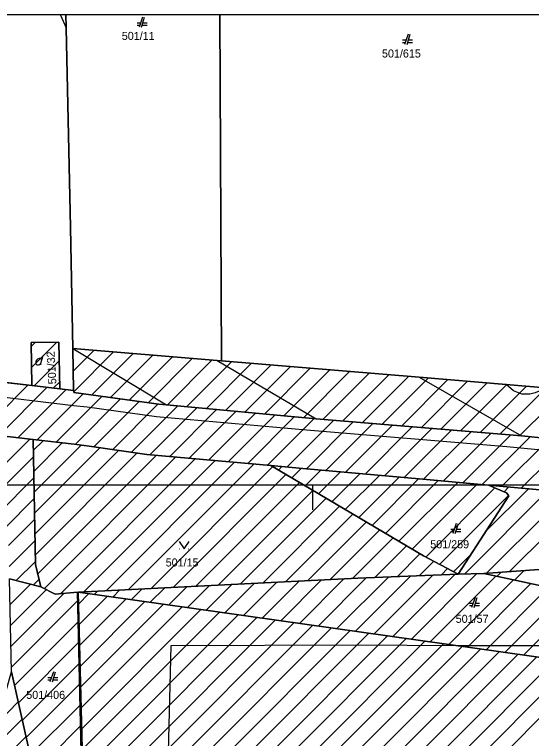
# Model space of a CAD drawing. Extents: x -264309 to -263505, y -1242443 to -1241763.
# Drawn here: x -263955.2 to -263852.2, y -1242101 to -1241957 of the extents above; entities that cross this region are included whole.
import ezdxf

# ---------------------------------------------------------------- set-up
doc = ezdxf.new("R2010")
doc.units = 0
for name, color, linetype in [('KFA_SO_50-2_POZIARNY_VODOVOD_TRASA', 7, 'Continuous'), ('KN_2019_08_16_KLADPAR', 7, 'Continuous'), ('KN_2019_08_16_ZAPPAR', 7, 'Continuous'), ('RAM_NA_TLAC_10xA4_1-500', 7, 'Continuous'), ('SRAFY_PARCELY', 7, 'Continuous')]:
    doc.layers.add(name, color=color, linetype=linetype)

msp = doc.modelspace()

# ---------------------------------------------------------------- linework, layer by layer
at = {"layer": 'KFA_SO_50-2_POZIARNY_VODOVOD_TRASA'}
msp.add_lwpolyline([(-263924.93, -1242185.13), (-263924.15, -1242197.09), (-263924.3, -1242220.9), (-263924.1, -1242250.12), (-263913.99, -1242249.8), (-263886.91, -1242249.88), (-263867.71, -1242249.83), (-263837.26, -1242249.84), (-263828.16, -1242249.9), (-263787.99, -1242250.03), (-263788.2, -1242220.84), (-263788.2, -1242200.51), (-263788.09, -1242179.92), (-263788.06, -1242148.96), (-263787.92, -1242127.95), (-263787.95, -1242110.97), (-263788.13, -1242082.54), (-263828.43, -1242082.72), (-263836.78, -1242082.56), (-263867.31, -1242082.61), (-263886.71, -1242082.47), (-263924.08, -1242082.61), (-263924.64, -1242106.32), (-263924.48, -1242117.43)], close=True, dxfattribs=at)
at = {"layer": 'KN_2019_08_16_KLADPAR'}
for p, q in [((-263979.18, -1241956.96), (-263944.96, -1241956.96)), ((-263944.96, -1241956.96), (-263944.89, -1241959.62)), ((-263944.89, -1241959.62), (-263944.96, -1241956.96)), ((-263944.96, -1241956.96), (-263914.3, -1241956.96)), ((-263929.7, -1241957.48), (-263930.4, -1241959.48)), ((-263929.9, -1241959.48), (-263929.3, -1241957.48)), ((-263914.3, -1241956.96), (-263830.29, -1241956.96)), ((-263914, -1242025.89), (-263914.3, -1241956.96)), ((-263914.3, -1241956.96), (-263914, -1242025.89)), ((-263930.12, -1241958.68), (-263930.8, -1241958.68)), ((-263930.8, -1241959.08), (-263930.26, -1241959.08)), ((-263929.78, -1241959.08), (-263928.8, -1241959.08)), ((-263928.8, -1241958.68), (-263929.66, -1241958.68)), ((-263944.89, -1241959.62), (-263944.09, -1241999.37)), ((-263944.09, -1241999.37), (-263944.89, -1241959.62)), ((-263876.81, -1241960.9), (-263877.51, -1241962.9)), ((-263877.01, -1241962.9), (-263876.41, -1241960.9)), ((-263877.23, -1241962.1), (-263877.91, -1241962.1)), ((-263877.91, -1241962.5), (-263877.37, -1241962.5)), ((-263876.89, -1241962.5), (-263875.91, -1241962.5)), ((-263875.91, -1241962.1), (-263876.77, -1241962.1)), ((-263944.09, -1241999.37), (-263943.61, -1242023.45)), ((-263943.61, -1242023.45), (-263944.09, -1241999.37)), ((-263946.36, -1242022.14), (-263951.91, -1242022.22)), ((-263951.91, -1242022.22), (-263951.74, -1242030.76)), ((-263946.18, -1242031.43), (-263946.36, -1242022.14)), ((-263943.61, -1242023.45), (-263943.43, -1242031.76)), ((-263914.84, -1242025.82), (-263943.61, -1242023.45)), ((-263949.79, -1242025.7), (-263949.52, -1242024.8)), ((-263914, -1242025.89), (-263914.84, -1242025.82)), ((-263874.62, -1242029.15), (-263914, -1242025.89)), ((-263951.74, -1242030.76), (-263970.71, -1242028.65)), ((-263857.26, -1242030.58), (-263874.62, -1242029.15)), ((-263849.43, -1242031.23), (-263857.26, -1242030.58)), ((-263943.43, -1242031.76), (-263946.18, -1242031.43)), ((-263867.19, -1242058.24), (-263867.89, -1242060.24)), ((-263867.39, -1242060.24), (-263866.79, -1242058.24)), ((-263867.61, -1242059.44), (-263868.29, -1242059.44)), ((-263868.29, -1242059.84), (-263867.75, -1242059.84)), ((-263867.27, -1242059.84), (-263866.29, -1242059.84)), ((-263866.29, -1242059.44), (-263867.15, -1242059.44)), ((-263922.36, -1242063.31), (-263922.26, -1242063.31)), ((-263920.56, -1242063.31), (-263920.46, -1242063.31)), ((-263863.45, -1242072.99), (-263864.15, -1242074.99)), ((-263863.65, -1242074.99), (-263863.05, -1242072.99)), ((-263863.87, -1242074.19), (-263864.55, -1242074.19)), ((-263862.55, -1242074.19), (-263863.41, -1242074.19)), ((-263864.55, -1242074.59), (-263864.01, -1242074.59)), ((-263863.53, -1242074.59), (-263862.55, -1242074.59)), ((-263947.45, -1242087.77), (-263948.15, -1242089.77)), ((-263947.65, -1242089.77), (-263947.05, -1242087.77)), ((-263947.87, -1242088.97), (-263948.55, -1242088.97)), ((-263948.55, -1242089.37), (-263948.01, -1242089.37)), ((-263947.53, -1242089.37), (-263946.55, -1242089.37)), ((-263946.55, -1242088.97), (-263947.41, -1242088.97))]:
    msp.add_line(p, q, dxfattribs=at)
for points in [[(-263951.74, -1242030.76), (-263951.91, -1242022.22), (-263946.36, -1242022.14), (-263946.18, -1242031.43)], [(-263859.25, -1242051.26), (-263857.2, -1242052.16), (-263856.75, -1242052.73), (-263866.84, -1242068.34), (-263873.71, -1242064.69), (-263904.14, -1242046.74), (-263897.8, -1242047.3), (-263874.58, -1242049.37), (-263860.75, -1242050.61)], [(-263860.75, -1242050.61), (-263838.09, -1242052.7), (-263834.98, -1242053.91), (-263833.09, -1242055.88), (-263832.11, -1242058.36), (-263832.17, -1242061), (-263833.22, -1242063.52), (-263835.57, -1242065.69), (-263837.8, -1242066.47), (-263861.71, -1242068.19), (-263866.84, -1242068.34), (-263856.75, -1242052.73), (-263857.2, -1242052.16), (-263859.25, -1242051.26)], [(-263866.84, -1242068.34), (-263861.71, -1242068.19), (-263831.68, -1242074.63), (-263824.48, -1242063.97), (-263825.06, -1242076), (-263823.41, -1242079.44), (-263822.15, -1242081.25), (-263808.5, -1242089.28), (-263825.79, -1242087.54), (-263827.51, -1242086.49), (-263831.22, -1242086.53), (-263833.02, -1242086.81), (-263846.54, -1242085.45), (-263942.54, -1242071.9), (-263913.4, -1242070.43), (-263886.83, -1242069.14)], [(-263945.92, -1242287.35), (-263949.74, -1242287.63), (-263949.41, -1242196.68), (-263949.38, -1242187.85), (-263949.49, -1242175.05), (-263949.55, -1242159.39), (-263950.14, -1242129.96), (-263950.48, -1242111.43), (-263955.8, -1242087.79), (-263956.24, -1242069.24), (-263949.96, -1242070.83), (-263947.13, -1242072.33), (-263942.68, -1242071.91), (-263941.47, -1242124.08), (-263944.59, -1242125.87), (-263946.11, -1242129.79), (-263945.51, -1242159.3), (-263945.41, -1242187.87)], [(-263942.54, -1242071.9), (-263846.54, -1242085.45), (-263846.27, -1242096.79), (-263846.29, -1242099.09), (-263845.63, -1242123.54), (-263845.17, -1242145.54), (-263890.62, -1242146.65), (-263890.76, -1242147.37), (-263921.62, -1242147.75), (-263934.65, -1242147.91), (-263935.23, -1242123.81), (-263941.18, -1242123.7)]]:
    msp.add_lwpolyline(points, close=True, dxfattribs=at)
for points in [[(-263773.94, -1242049.27), (-263789.68, -1242047.57), (-263790.18, -1242047.53), (-263806.03, -1242046.03), (-263821.84, -1242044.14), (-263837.98, -1242042.2), (-263848.99, -1242041.32), (-263854.22, -1242040.83), (-263895.14, -1242037.44), (-263924.96, -1242034.66), (-263926.48, -1242034.52), (-263943.42, -1242032.17), (-263943.43, -1242031.76), (-263943.61, -1242023.45), (-263914.84, -1242025.82), (-263914, -1242025.89), (-263874.62, -1242029.15), (-263857.26, -1242030.58), (-263849.43, -1242031.23), (-263836.79, -1242032.27), (-263829.96, -1242032.95), (-263750.04, -1242040.89)], [(-263949.97, -1242026.69), (-263949.97, -1242026.42), (-263949.79, -1242025.7), (-263949.88, -1242025.52), (-263950.06, -1242025.43), (-263950.33, -1242025.43), (-263950.6, -1242025.52), (-263950.78, -1242025.7), (-263950.96, -1242025.97), (-263950.96, -1242026.33), (-263950.87, -1242026.6), (-263950.69, -1242026.69), (-263950.42, -1242026.69), (-263950.24, -1242026.6), (-263949.97, -1242026.42)], [(-263970.71, -1242028.65), (-263951.74, -1242030.76), (-263946.18, -1242031.43), (-263943.43, -1242031.76), (-263943.42, -1242032.17), (-263926.48, -1242034.52), (-263924.96, -1242034.66), (-263895.14, -1242037.44), (-263854.22, -1242040.83), (-263848.99, -1242041.32), (-263837.98, -1242042.2), (-263821.84, -1242044.14), (-263806.03, -1242046.03), (-263790.18, -1242047.53), (-263789.68, -1242047.57), (-263773.94, -1242049.27)], [(-263958.98, -1242040.66), (-263951.52, -1242041.54), (-263951.02, -1242066.42), (-263949.96, -1242070.83), (-263956.24, -1242069.24)], [(-263838.09, -1242052.7), (-263860.75, -1242050.61), (-263874.58, -1242049.37), (-263897.8, -1242047.3), (-263904.14, -1242046.74), (-263928.83, -1242044.55), (-263940.32, -1242042.89), (-263943.31, -1242042.48), (-263951.52, -1242041.54), (-263958.98, -1242040.66)], [(-263941.47, -1242124.08), (-263942.68, -1242071.91), (-263947.13, -1242072.33), (-263949.96, -1242070.83), (-263951.02, -1242066.42), (-263951.52, -1242041.54), (-263943.31, -1242042.48), (-263940.32, -1242042.89), (-263928.83, -1242044.55), (-263904.14, -1242046.74), (-263873.71, -1242064.69), (-263866.84, -1242068.34), (-263886.83, -1242069.14), (-263913.4, -1242070.43), (-263942.54, -1242071.9), (-263941.18, -1242123.7)], [(-263922.41, -1242061.81), (-263921.41, -1242063.31), (-263920.41, -1242061.81)], [(-263831.68, -1242074.63), (-263861.71, -1242068.19), (-263837.8, -1242066.47)], [(-263970.22, -1242106.22), (-263970.24, -1242093.63), (-263970.38, -1242092.72), (-263963.73, -1242092.7), (-263963.72, -1242093.73), (-263959.83, -1242093.59), (-263956.8, -1242091.26), (-263955.8, -1242087.79), (-263950.48, -1242111.43)]]:
    msp.add_lwpolyline(points, dxfattribs=at)
at = {"layer": 'KN_2019_08_16_ZAPPAR'}
for p, q in [((-263943.61, -1242023.45), (-263924.96, -1242034.66)), ((-263914.84, -1242025.82), (-263895.14, -1242037.44)), ((-263874.62, -1242029.15), (-263854.22, -1242040.83)), ((-263852.57, -1242032.52), (-263854.16, -1242032.48))]:
    msp.add_line(p, q, dxfattribs=at)
for points in [[(-263946.2, -1241956.96), (-263946.07, -1241957.08), (-263944.89, -1241959.62)], [(-264009.05, -1242025.11), (-264007.06, -1242027.03), (-264004.88, -1242027.82), (-264001.52, -1242027.99), (-263958.32, -1242033), (-263951.68, -1242033.75), (-263943.48, -1242034.79), (-263940.72, -1242035.02), (-263926.91, -1242036.98), (-263897.04, -1242039.59), (-263857.13, -1242042.91), (-263837.1, -1242044.85)], [(-263854.16, -1242032.48), (-263855.79, -1242031.87), (-263857.26, -1242030.58)], [(-263849.43, -1242031.23), (-263850.37, -1242031.77), (-263851.47, -1242032.24), (-263852.57, -1242032.52)]]:
    msp.add_lwpolyline(points, dxfattribs=at)
at = {"layer": 'RAM_NA_TLAC_10xA4_1-500'}
msp.add_line((-263895.83, -1242050.54), (-263895.83, -1242055.54), dxfattribs=at)
msp.add_lwpolyline([(-264210.83, -1242050.54), (-264105.83, -1242050.54), (-264000.83, -1242050.54), (-263895.83, -1242050.54), (-263790.83, -1242050.54), (-263685.83, -1242050.54), (-263685.83, -1242199.04), (-263685.83, -1242347.54), (-263790.83, -1242347.54), (-263895.83, -1242347.54), (-264000.83, -1242347.54), (-264105.83, -1242347.54), (-264210.83, -1242347.54), (-264210.83, -1242199.04)], close=True, dxfattribs=at)
at = {"layer": 'SRAFY_PARCELY'}
for p, q in [((-263951.89, -1242023.02), (-263951.08, -1242022.21)), ((-263951.81, -1242027.18), (-263946.78, -1242022.15)), ((-263943.6, -1242023.76), (-263943.32, -1242023.47)), ((-263943.51, -1242027.91), (-263939.4, -1242023.8)), ((-263943.42, -1242032.06), (-263935.48, -1242024.12)), ((-263939.79, -1242032.67), (-263931.56, -1242024.44)), ((-263936.06, -1242033.19), (-263927.64, -1242024.77)), ((-263932.34, -1242033.71), (-263923.72, -1242025.09)), ((-263928.61, -1242034.22), (-263919.8, -1242025.41)), ((-263951.21, -1242030.82), (-263946.29, -1242025.9)), ((-263924.82, -1242034.67), (-263915.88, -1242025.73)), ((-263920.94, -1242035.03), (-263911.96, -1242026.06)), ((-263917.06, -1242035.4), (-263908.04, -1242026.38)), ((-263913.18, -1242035.76), (-263904.13, -1242026.71)), ((-263909.3, -1242036.12), (-263900.21, -1242027.03)), ((-263905.42, -1242036.48), (-263896.29, -1242027.36)), ((-263901.53, -1242036.84), (-263892.37, -1242027.68)), ((-263897.65, -1242037.21), (-263888.45, -1242028)), ((-263893.76, -1242037.55), (-263884.53, -1242028.33)), ((-263889.84, -1242037.88), (-263880.62, -1242028.65)), ((-263885.92, -1242038.2), (-263876.7, -1242028.98)), ((-263882.01, -1242038.53), (-263872.78, -1242029.3)), ((-263878.09, -1242038.85), (-263868.86, -1242029.62)), ((-263962.12, -1242040.29), (-263952.5, -1242030.67)), ((-263958.32, -1242040.74), (-263948.71, -1242031.12)), ((-263947.43, -1242031.28), (-263946.21, -1242030.06)), ((-263874.17, -1242039.18), (-263864.94, -1242029.95)), ((-263870.25, -1242039.5), (-263861.02, -1242030.27)), ((-263866.33, -1242039.83), (-263857.1, -1242030.59)), ((-263862.42, -1242040.15), (-263853.18, -1242030.92)), ((-263954.53, -1242041.19), (-263944.92, -1242031.58)), ((-263950.73, -1242041.63), (-263941.53, -1242032.43)), ((-263858.5, -1242040.48), (-263849.27, -1242031.24)), ((-263854.58, -1242040.8), (-263845.35, -1242031.57)), ((-263946.92, -1242042.07), (-263937.81, -1242032.95)), ((-263943.12, -1242042.51), (-263934.08, -1242033.47)), ((-263939.4, -1242043.02), (-263930.36, -1242033.98)), ((-263935.69, -1242043.56), (-263926.63, -1242034.5)), ((-263931.98, -1242044.09), (-263922.75, -1242034.87)), ((-263928.25, -1242044.6), (-263918.87, -1242035.23)), ((-263924.35, -1242044.95), (-263914.99, -1242035.59)), ((-263920.45, -1242045.29), (-263911.11, -1242035.95)), ((-263916.56, -1242045.64), (-263907.23, -1242036.31)), ((-263912.66, -1242045.98), (-263903.35, -1242036.67)), ((-263908.76, -1242046.33), (-263899.47, -1242037.04)), ((-263904.87, -1242046.68), (-263895.59, -1242037.4)), ((-263900.97, -1242047.02), (-263891.67, -1242037.73)), ((-263897.07, -1242047.37), (-263887.76, -1242038.05)), ((-263893.17, -1242047.71), (-263883.84, -1242038.38)), ((-263889.28, -1242048.06), (-263879.92, -1242038.7)), ((-263885.38, -1242048.41), (-263876, -1242039.03)), ((-263881.49, -1242048.75), (-263872.08, -1242039.35)), ((-263877.59, -1242049.1), (-263868.17, -1242039.67)), ((-263873.7, -1242049.45), (-263864.25, -1242040)), ((-263869.8, -1242049.8), (-263860.33, -1242040.32)), ((-263865.91, -1242050.15), (-263856.41, -1242040.65)), ((-263862.02, -1242050.5), (-263852.51, -1242040.99)), ((-263963.98, -1242053.27), (-263952.17, -1242041.46)), ((-263951.48, -1242043.71), (-263949.53, -1242041.77)), ((-263951.39, -1242047.87), (-263945.73, -1242042.2)), ((-263951.31, -1242052.03), (-263941.95, -1242042.67)), ((-263858.13, -1242050.85), (-263848.63, -1242041.35)), ((-263854.25, -1242051.21), (-263844.7, -1242041.66)), ((-263951.23, -1242056.19), (-263938.23, -1242043.19)), ((-263951.14, -1242060.35), (-263934.52, -1242043.73)), ((-263961.07, -1242054.6), (-263951.45, -1242044.98)), ((-263951.06, -1242064.51), (-263930.81, -1242044.26)), ((-263950.58, -1242068.27), (-263927.02, -1242044.71)), ((-263949.26, -1242071.2), (-263923.12, -1242045.06)), ((-263946.05, -1242072.23), (-263919.23, -1242045.4)), ((-263941.42, -1242071.84), (-263915.33, -1242045.75)), ((-263936.96, -1242071.62), (-263911.43, -1242046.09)), ((-263932.49, -1242071.39), (-263907.53, -1242046.44)), ((-263928.02, -1242071.17), (-263903.8, -1242046.94)), ((-263902.65, -1242047.62), (-263901.97, -1242046.93)), ((-263899.98, -1242049.19), (-263898.07, -1242047.28)), ((-263897.32, -1242050.77), (-263894.17, -1242047.62)), ((-263894.65, -1242052.34), (-263890.28, -1242047.97)), ((-263891.98, -1242053.91), (-263886.38, -1242048.32)), ((-263958.48, -1242056.25), (-263951.37, -1242049.14)), ((-263923.55, -1242070.94), (-263901.13, -1242048.52)), ((-263889.31, -1242055.49), (-263882.49, -1242048.67)), ((-263886.64, -1242057.06), (-263878.59, -1242049.01)), ((-263883.97, -1242058.64), (-263874.7, -1242049.36)), ((-263881.3, -1242060.21), (-263870.8, -1242049.71)), ((-263919.08, -1242070.72), (-263898.46, -1242050.09)), ((-263878.64, -1242061.78), (-263866.91, -1242050.06)), ((-263875.97, -1242063.36), (-263863.02, -1242050.41)), ((-263873.28, -1242064.92), (-263859.51, -1242051.15)), ((-263861.36, -1242059.86), (-263852.84, -1242051.34)), ((-263860.64, -1242050.66), (-263860.61, -1242050.62)), ((-263857.69, -1242051.95), (-263856.72, -1242050.98)), ((-263914.62, -1242070.49), (-263895.79, -1242051.67)), ((-263870.51, -1242066.39), (-263856.8, -1242052.67)), ((-263865.56, -1242068.3), (-263848.95, -1242051.7)), ((-263861.16, -1242068.15), (-263845.07, -1242052.06)), ((-263856.59, -1242067.82), (-263841.19, -1242052.41)), ((-263957.13, -1242059.15), (-263951.28, -1242053.3)), ((-263910.16, -1242070.27), (-263893.12, -1242053.24)), ((-263905.7, -1242070.06), (-263890.45, -1242054.81)), ((-263901.24, -1242069.84), (-263887.78, -1242056.39)), ((-263956.39, -1242062.65), (-263951.2, -1242057.46)), ((-263896.78, -1242069.62), (-263885.12, -1242057.96)), ((-263892.32, -1242069.41), (-263882.45, -1242059.54)), ((-263887.86, -1242069.19), (-263879.78, -1242061.11)), ((-263956.3, -1242066.8), (-263951.12, -1242061.62)), ((-263883.43, -1242069), (-263877.11, -1242062.68)), ((-263879.01, -1242068.83), (-263874.44, -1242064.26)), ((-263954.85, -1242069.59), (-263951.03, -1242065.78)), ((-263874.59, -1242068.65), (-263871.7, -1242065.76)), ((-263867.74, -1242067.86), (-263864.32, -1242064.44)), ((-263870.17, -1242068.47), (-263868.93, -1242067.23)), ((-263883.57, -1242080.22), (-263871.89, -1242068.54)), ((-263879.85, -1242080.75), (-263867.47, -1242068.37)), ((-263876.14, -1242081.27), (-263863.09, -1242068.23)), ((-263859.06, -1242068.76), (-263858.25, -1242067.94)), ((-263855.57, -1242069.51), (-263853.68, -1242067.61)), ((-263951.46, -1242070.45), (-263950.32, -1242069.31)), ((-263909.6, -1242076.55), (-263902.97, -1242069.92)), ((-263905.88, -1242077.07), (-263898.51, -1242069.71)), ((-263902.16, -1242077.6), (-263894.05, -1242069.49)), ((-263898.44, -1242078.12), (-263889.59, -1242069.27)), ((-263894.72, -1242078.65), (-263885.15, -1242069.07)), ((-263891.01, -1242079.17), (-263880.73, -1242068.9)), ((-263887.29, -1242079.7), (-263876.31, -1242068.72)), ((-263872.42, -1242081.8), (-263859.32, -1242068.7)), ((-263868.7, -1242082.32), (-263855.83, -1242069.45)), ((-263956.12, -1242074.41), (-263952.02, -1242070.31)), ((-263956.02, -1242078.55), (-263948.87, -1242071.41)), ((-263935.62, -1242072.88), (-263934.23, -1242071.48)), ((-263931.9, -1242073.4), (-263929.76, -1242071.26)), ((-263928.19, -1242073.93), (-263925.29, -1242071.03)), ((-263924.47, -1242074.45), (-263920.82, -1242070.8)), ((-263920.75, -1242074.98), (-263916.35, -1242070.58)), ((-263917.03, -1242075.5), (-263911.89, -1242070.36)), ((-263913.31, -1242076.03), (-263907.43, -1242070.14)), ((-263864.98, -1242082.85), (-263852.34, -1242070.2)), ((-263861.26, -1242083.37), (-263848.84, -1242070.95)), ((-263955.92, -1242082.7), (-263945.39, -1242072.17)), ((-263942.65, -1242073.07), (-263942.51, -1242072.93)), ((-263942.48, -1242074.29), (-263940.39, -1242072.2)), ((-263942.37, -1242078.42), (-263936.68, -1242072.73)), ((-263939.34, -1242072.35), (-263938.69, -1242071.71)), ((-263857.55, -1242083.9), (-263845.35, -1242071.7)), ((-263853.83, -1242084.42), (-263841.85, -1242072.45)), ((-263955.82, -1242086.84), (-263942.64, -1242073.66)), ((-263942.26, -1242082.55), (-263932.96, -1242073.25)), ((-263942.15, -1242086.69), (-263929.24, -1242073.78)), ((-263942.04, -1242090.82), (-263925.52, -1242074.3)), ((-263941.93, -1242094.96), (-263921.8, -1242074.83)), ((-263941.83, -1242099.09), (-263918.09, -1242075.35)), ((-263941.72, -1242103.22), (-263914.37, -1242075.88)), ((-263942.56, -1242077.22), (-263942.4, -1242077.07)), ((-263941.61, -1242107.36), (-263910.65, -1242076.4)), ((-263941.5, -1242111.49), (-263906.93, -1242076.93)), ((-263955.2, -1242090.46), (-263942.54, -1242077.81)), ((-263941.39, -1242115.63), (-263903.22, -1242077.45)), ((-263941.28, -1242119.76), (-263899.5, -1242077.98)), ((-263940.98, -1242123.7), (-263895.78, -1242078.5)), ((-263936.82, -1242123.78), (-263892.06, -1242079.02)), ((-263935.17, -1242126.37), (-263888.34, -1242079.55)), ((-263935.07, -1242130.52), (-263884.63, -1242080.07)), ((-263942.46, -1242081.36), (-263942.3, -1242081.2)), ((-263934.97, -1242134.66), (-263880.91, -1242080.6)), ((-263934.87, -1242138.8), (-263877.19, -1242081.12)), ((-263934.77, -1242142.95), (-263873.47, -1242081.65)), ((-263954.42, -1242093.92), (-263942.45, -1242081.95)), ((-263934.67, -1242147.09), (-263869.75, -1242082.17)), ((-263931.21, -1242147.87), (-263866.04, -1242082.7)), ((-263926.91, -1242147.81), (-263862.32, -1242083.22)), ((-263922.62, -1242147.76), (-263858.6, -1242083.75)), ((-263918.32, -1242147.71), (-263854.88, -1242084.27)), ((-263942.36, -1242085.51), (-263942.19, -1242085.33)), ((-263914.02, -1242147.66), (-263851.17, -1242084.8)), ((-263909.73, -1242147.6), (-263847.45, -1242085.32)), ((-263953.64, -1242097.39), (-263942.35, -1242086.1)), ((-263905.43, -1242147.55), (-263846.47, -1242088.58)), ((-263952.86, -1242100.85), (-263942.25, -1242090.25)), ((-263942.27, -1242089.66), (-263942.08, -1242089.47)), ((-263901.14, -1242147.5), (-263846.37, -1242092.73)), ((-263975.6, -1242114.85), (-263954.47, -1242093.72)), ((-263952.08, -1242104.31), (-263942.16, -1242094.39)), ((-263942.17, -1242093.8), (-263941.97, -1242093.6)), ((-263962.73, -1242106.22), (-263953.69, -1242097.18)), ((-263951.3, -1242107.78), (-263942.06, -1242098.54)), ((-263942.08, -1242097.95), (-263941.86, -1242097.74)), ((-263958.48, -1242106.21), (-263952.91, -1242100.64))]:
    msp.add_line(p, q, dxfattribs=at)

# ---------------------------------------------------------------- texts
at = {"layer": 'KN_2019_08_16_KLADPAR'}
for s, p in [('501/11', (-263933.84, -1241962.02)), ('501/615', (-263882, -1241965.52)), ('501/259', (-263872.38, -1242063.18)), ('501/15', (-263925.09, -1242066.8)), ('501/57', (-263867.31, -1242078.02)), ('501/406', (-263952.87, -1242093.15))]:
    msp.add_text(s, height=1.6, dxfattribs=at).set_placement(p)
msp.add_text('501/32', height=1.6, rotation=93.2775, dxfattribs=at).set_placement((-263946.86, -1242030.49))

doc.saveas('drawing.dxf')
